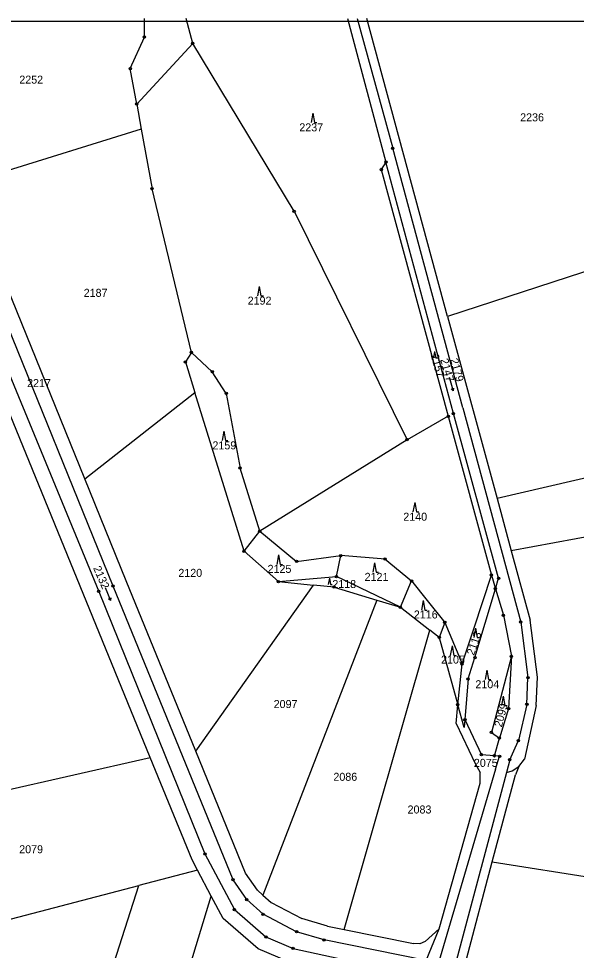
# Model space of a CAD drawing. Extents: x -566461 to -565197, y -1096302 to -1095706.
# Drawn here: x -566039.2 to -565802.3, y -1096101.6 to -1095706 of the extents above; entities that cross this region are included whole.
import ezdxf

# ---------------------------------------------------------------- set-up
doc = ezdxf.new("R2010")
doc.units = 0
for name, color, linetype in [('Vrstva 1', 7, 'Continuous'), ('Vrstva 18', 7, 'Continuous'), ('Vrstva 24', 7, 'Continuous'), ('Vrstva 25', 7, 'Continuous'), ('Vrstva 63', 7, 'Continuous')]:
    doc.layers.add(name, color=color, linetype=linetype)

msp = doc.modelspace()

# ---------------------------------------------------------------- linework, layer by layer
at = {"layer": 'Vrstva 1'}
for p, q in [((-565985.8, -1095713.8), (-565985.75, -1095705.99)), ((-565965.29, -1095716.53), (-565968.02, -1095705.99)), ((-565899.59, -1095705.99), (-565883.2, -1095766.88)), ((-565895.44, -1095705.99), (-565880.3, -1095761.04)), ((-565857.02, -1095832.44), (-565891.34, -1095705.99)), ((-565991.82, -1095727.21), (-565985.8, -1095713.8)), ((-565989.09, -1095742.24), (-565965.29, -1095716.53)), ((-565922.2, -1095787.77), (-565965.29, -1095716.53)), ((-565989.09, -1095742.24), (-565991.82, -1095727.21)), ((-565989.09, -1095742.24), (-565987.16, -1095752.85)), ((-565987.16, -1095752.85), (-566062.52, -1095776.24)), ((-565987.16, -1095752.85), (-565982.54, -1095778.25)), ((-565850.51, -1095871.29), (-565880.3, -1095761.04)), ((-565883.2, -1095766.88), (-565885.21, -1095770.05)), ((-565854.53, -1095873.66), (-565883.2, -1095766.88)), ((-565885.21, -1095770.05), (-565856.75, -1095874.83)), ((-566011.15, -1095901.4), (-566060.56, -1095779.67)), ((-565965.83, -1095847.73), (-565982.54, -1095778.25)), ((-566073.46, -1095783.73), (-566005.23, -1095949.18)), ((-565999.14, -1095946.93), (-566066.64, -1095780.66)), ((-565922.2, -1095787.77), (-565874.23, -1095884.76)), ((-565738.18, -1095793.75), (-565857.02, -1095832.44)), ((-565857.02, -1095832.44), (-565836.03, -1095909.77)), ((-565983.37, -1096019.72), (-566053.24, -1095848.98)), ((-565965.83, -1095847.73), (-565968.4, -1095851.75)), ((-565965.83, -1095847.73), (-565957.02, -1095855.93)), ((-565968.4, -1095851.75), (-565964.37, -1095864.76)), ((-565951.05, -1095865.15), (-565957.02, -1095855.93)), ((-566011.15, -1095901.4), (-565964.37, -1095864.76)), ((-565943.5, -1095932.13), (-565964.37, -1095864.76)), ((-565951.05, -1095865.15), (-565945.16, -1095896.83)), ((-565850.51, -1095871.29), (-565825.94, -1095962.21)), ((-565856.75, -1095874.83), (-565874.23, -1095884.76)), ((-565856.75, -1095874.83), (-565838.43, -1095942.26)), ((-565835.34, -1095943.62), (-565854.53, -1095873.66)), ((-565718.36, -1095882.24), (-565836.03, -1095909.77)), ((-565874.23, -1095884.76), (-565936.81, -1095923.63)), ((-565936.81, -1095923.63), (-565945.16, -1095896.83)), ((-565993.59, -1095944.66), (-566011.15, -1095901.4)), ((-565836.03, -1095909.77), (-565830.02, -1095931.91)), ((-565718.91, -1095911.52), (-565830.02, -1095931.91)), ((-565943.5, -1095932.13), (-565936.81, -1095923.63)), ((-565936.81, -1095923.63), (-565921.15, -1095936.42)), ((-565928.92, -1095944.99), (-565943.5, -1095932.13)), ((-565921.15, -1095936.42), (-565902.44, -1095933.99)), ((-565904.24, -1095942.9), (-565902.44, -1095933.99)), ((-565883.57, -1095935.48), (-565902.44, -1095933.99)), ((-565830.02, -1095931.91), (-565822.01, -1095961.42)), ((-565883.57, -1095935.48), (-565872.35, -1095944.72)), ((-565845.8, -1095964.6), (-565838.43, -1095942.26)), ((-565838.43, -1095942.26), (-565836.68, -1095948.08)), ((-565963.96, -1096017.08), (-565993.59, -1095944.66)), ((-565963.96, -1096017.08), (-565914.03, -1095946.48)), ((-565928.92, -1095944.99), (-565904.24, -1095942.9)), ((-565928.92, -1095944.99), (-565914.03, -1095946.48)), ((-565905.24, -1095947.36), (-565914.03, -1095946.48)), ((-565877.07, -1095955.94), (-565904.24, -1095942.9)), ((-565877.07, -1095955.94), (-565872.35, -1095944.72)), ((-565872.35, -1095944.72), (-565865.64, -1095953.07)), ((-565836.68, -1095948.08), (-565835.34, -1095943.62)), ((-566005.23, -1095949.18), (-565960.14, -1096060.64)), ((-565948.12, -1096071.63), (-565999.14, -1095946.93)), ((-565905.24, -1095947.36), (-565887.08, -1095952.89)), ((-565845.4, -1095977.26), (-565836.68, -1095948.08)), ((-565836.68, -1095948.08), (-565833.29, -1095959.33)), ((-565887.08, -1095952.89), (-565935.5, -1096078.14)), ((-565887.08, -1095952.89), (-565877.07, -1095955.94)), ((-565865.64, -1095953.07), (-565858.2, -1095962.33)), ((-565877.07, -1095955.94), (-565864.53, -1095965.67)), ((-565833.29, -1095959.33), (-565829.89, -1095976.68)), ((-565825.94, -1095962.21), (-565822.87, -1095985.77)), ((-565818.86, -1095985.6), (-565822.01, -1095961.42)), ((-565901, -1096092.75), (-565864.53, -1095965.67)), ((-565860.56, -1095968.75), (-565864.53, -1095965.67)), ((-565858.2, -1095962.33), (-565860.56, -1095968.75)), ((-565858.2, -1095962.33), (-565853.39, -1095973.87)), ((-565850.86, -1095979.94), (-565845.8, -1095964.6)), ((-565860.56, -1095968.75), (-565852.69, -1095997.27)), ((-565853.39, -1095973.87), (-565850.86, -1095979.94)), ((-565848.34, -1095986.31), (-565845.4, -1095977.26)), ((-565829.89, -1095976.68), (-565838.4, -1096009.07)), ((-565829.89, -1095976.68), (-565831.09, -1095998.91)), ((-565852.69, -1095997.27), (-565850.86, -1095979.94)), ((-565823.36, -1095997.16), (-565822.87, -1095985.77)), ((-565819.41, -1095997.69), (-565818.86, -1095985.6)), ((-565848.34, -1095986.31), (-565849.7, -1096003.6)), ((-565853.32, -1096005.31), (-565852.69, -1095997.27)), ((-565849.96, -1096006.91), (-565852.69, -1095997.27)), ((-565823.36, -1095997.16), (-565826.91, -1096012.51)), ((-565819.41, -1095997.69), (-565824.4, -1096020.34)), ((-565831.09, -1095998.91), (-565835.01, -1096011.43)), ((-565853.32, -1096005.31), (-565845.3, -1096022.3)), ((-565849.7, -1096003.6), (-565849.96, -1096006.91)), ((-565849.7, -1096003.6), (-565842.66, -1096018.51)), ((-565838.4, -1096009.07), (-565835.01, -1096011.43)), ((-565837.12, -1096018.99), (-565835.01, -1096011.43)), ((-565828.33, -1096015.6), (-565826.91, -1096012.51)), ((-565942.81, -1096068.77), (-565963.96, -1096017.08)), ((-565830.65, -1096020.64), (-565828.33, -1096015.6)), ((-566099.43, -1096046), (-565983.37, -1096019.72)), ((-565965.58, -1096063.19), (-565983.37, -1096019.72)), ((-565837.12, -1096018.99), (-565842.66, -1096018.51)), ((-565834.95, -1096019.18), (-565837.12, -1096018.99)), ((-565836.72, -1096024.67), (-565834.95, -1096019.18)), ((-565830.65, -1096020.64), (-565832.07, -1096026.09)), ((-565826.72, -1096023.51), (-565824.4, -1096020.34)), ((-565836.72, -1096024.67), (-565860.88, -1096106.94)), ((-565845.3, -1096022.3), (-565843.15, -1096026.07)), ((-565832.07, -1096026.09), (-565829.55, -1096025.32)), ((-565829.55, -1096025.32), (-565826.72, -1096023.51)), ((-565826.72, -1096023.51), (-565828.2, -1096027.12)), ((-565832.07, -1096026.09), (-565854, -1096108.33)), ((-565843.23, -1096030.62), (-565843.15, -1096026.07)), ((-565838.03, -1096063.98), (-565828.2, -1096027.12)), ((-565860.59, -1096092.38), (-565843.23, -1096030.62)), ((-565960.14, -1096060.64), (-565947.56, -1096084.25)), ((-565963.24, -1096067.58), (-565965.58, -1096063.19)), ((-565849.04, -1096105.26), (-565838.03, -1096063.98)), ((-565838.03, -1096063.98), (-565736.97, -1096079.98)), ((-565963.24, -1096067.58), (-565988.25, -1096074.11)), ((-565957.4, -1096078.54), (-565963.24, -1096067.58)), ((-565937.82, -1096076.07), (-565942.81, -1096068.77)), ((-565942.36, -1096080.06), (-565948.12, -1096071.63)), ((-566049.51, -1096090.1), (-565988.25, -1096074.11)), ((-566039.72, -1096234.72), (-565988.25, -1096074.11)), ((-565937.82, -1096076.07), (-565935.5, -1096078.14)), ((-566002.86, -1096227.33), (-565957.4, -1096078.54)), ((-565952.33, -1096088.05), (-565957.4, -1096078.54)), ((-565935.41, -1096086.27), (-565942.36, -1096080.06)), ((-565935.5, -1096078.14), (-565931.97, -1096081.29)), ((-565947.56, -1096084.25), (-565934.22, -1096095.86)), ((-565931.97, -1096081.29), (-565918.93, -1096088.11)), ((-565937.44, -1096101.01), (-565952.33, -1096088.05)), ((-565921.19, -1096093.7), (-565935.41, -1096086.27)), ((-565908.08, -1096091.32), (-565918.93, -1096088.11)), ((-565908.08, -1096091.32), (-565901, -1096092.75)), ((-565901, -1096092.75), (-565871.5, -1096098.69)), ((-565860.59, -1096092.38), (-565866.49, -1096097.81)), ((-565866.09, -1096105.89), (-565860.59, -1096092.38)), ((-565934.22, -1096095.86), (-565922.65, -1096100.77)), ((-565909.52, -1096097.15), (-565921.19, -1096093.7)), ((-565922.65, -1096100.77), (-565855.22, -1096115.35)), ((-565866.09, -1096105.89), (-565909.52, -1096097.15)), ((-565868.87, -1096098.76), (-565871.5, -1096098.69)), ((-565866.49, -1096097.81), (-565868.87, -1096098.76)), ((-565924.47, -1096106.51), (-565937.44, -1096101.01))]:
    msp.add_line(p, q, dxfattribs=at)
at = {"layer": 'Vrstva 24'}
for centre, radius in [((-565985.8, -1095713.8), 0.5), ((-565985.8, -1095713.8), 0.0327), ((-565965.29, -1095716.53), 0.5), ((-565965.29, -1095716.53), 0.0327), ((-565991.82, -1095727.21), 0.5), ((-565991.82, -1095727.21), 0.0327), ((-565989.09, -1095742.24), 0.5), ((-565989.09, -1095742.24), 0.0327), ((-565880.3, -1095761.04), 0.5), ((-565880.3, -1095761.04), 0.0327), ((-565883.2, -1095766.88), 0.5), ((-565883.2, -1095766.88), 0.0327), ((-565885.21, -1095770.05), 0.5), ((-565885.21, -1095770.05), 0.0327), ((-565982.54, -1095778.25), 0.5), ((-565982.54, -1095778.25), 0.0327), ((-565922.2, -1095787.77), 0.5), ((-565922.2, -1095787.77), 0.0327), ((-565965.83, -1095847.73), 0.5), ((-565968.4, -1095851.75), 0.5), ((-565965.83, -1095847.73), 0.0327), ((-565968.4, -1095851.75), 0.0327), ((-565957.02, -1095855.93), 0.5), ((-565957.02, -1095855.93), 0.0327), ((-565951.05, -1095865.15), 0.5), ((-565951.05, -1095865.15), 0.0327), ((-565856.75, -1095874.83), 0.5), ((-565856.75, -1095874.83), 0.0327), ((-565854.53, -1095873.66), 0.5), ((-565854.53, -1095873.66), 0.0327), ((-565874.23, -1095884.76), 0.5), ((-565874.23, -1095884.76), 0.0327), ((-565945.16, -1095896.83), 0.5), ((-565945.16, -1095896.83), 0.0327), ((-565936.81, -1095923.63), 0.5), ((-565936.81, -1095923.63), 0.0327), ((-565943.5, -1095932.13), 0.5), ((-565943.5, -1095932.13), 0.0327), ((-565902.44, -1095933.99), 0.5), ((-565902.44, -1095933.99), 0.0327), ((-565921.15, -1095936.42), 0.5), ((-565921.15, -1095936.42), 0.0327), ((-565883.57, -1095935.48), 0.5), ((-565883.57, -1095935.48), 0.0327), ((-565904.24, -1095942.9), 0.5), ((-565838.43, -1095942.26), 0.5), ((-565838.43, -1095942.26), 0.0327), ((-565999.14, -1095946.93), 0.5), ((-565928.92, -1095944.99), 0.5), ((-565928.92, -1095944.99), 0.0327), ((-565904.24, -1095942.9), 0.0327), ((-565872.35, -1095944.72), 0.5), ((-565872.35, -1095944.72), 0.0327), ((-565835.34, -1095943.62), 0.5), ((-565835.34, -1095943.62), 0.0327), ((-566005.23, -1095949.18), 0.5), ((-566005.23, -1095949.18), 0.0327), ((-565999.14, -1095946.93), 0.0327), ((-565905.24, -1095947.36), 0.5), ((-565905.24, -1095947.36), 0.0327), ((-565836.68, -1095948.08), 0.5), ((-565836.68, -1095948.08), 0.0327), ((-565877.07, -1095955.94), 0.5), ((-565877.07, -1095955.94), 0.0327), ((-565858.2, -1095962.33), 0.5), ((-565858.2, -1095962.33), 0.0327), ((-565833.29, -1095959.33), 0.5), ((-565833.29, -1095959.33), 0.0327), ((-565825.94, -1095962.21), 0.5), ((-565825.94, -1095962.21), 0.0327), ((-565860.56, -1095968.75), 0.5), ((-565860.56, -1095968.75), 0.0327), ((-565845.4, -1095977.26), 0.5), ((-565845.4, -1095977.26), 0.0327), ((-565829.89, -1095976.68), 0.5), ((-565829.89, -1095976.68), 0.0327), ((-565850.86, -1095979.94), 0.5), ((-565850.86, -1095979.94), 0.0327), ((-565848.34, -1095986.31), 0.5), ((-565822.87, -1095985.77), 0.5), ((-565822.87, -1095985.77), 0.0327), ((-565848.34, -1095986.31), 0.0327), ((-565852.69, -1095997.27), 0.5), ((-565852.69, -1095997.27), 0.0327), ((-565823.36, -1095997.16), 0.5), ((-565823.36, -1095997.16), 0.0327), ((-565831.09, -1095998.91), 0.5), ((-565831.09, -1095998.91), 0.0327), ((-565849.7, -1096003.6), 0.5), ((-565849.7, -1096003.6), 0.0327), ((-565838.4, -1096009.07), 0.5), ((-565838.4, -1096009.07), 0.0327), ((-565835.01, -1096011.43), 0.5), ((-565835.01, -1096011.43), 0.0327), ((-565826.91, -1096012.51), 0.5), ((-565826.91, -1096012.51), 0.0327), ((-565842.66, -1096018.51), 0.5), ((-565842.66, -1096018.51), 0.0327), ((-565837.12, -1096018.99), 0.5), ((-565837.12, -1096018.99), 0.0327), ((-565834.95, -1096019.18), 0.5), ((-565834.95, -1096019.18), 0.0327), ((-565830.65, -1096020.64), 0.5), ((-565830.65, -1096020.64), 0.0327), ((-565960.14, -1096060.64), 0.5), ((-565960.14, -1096060.64), 0.0327), ((-565948.12, -1096071.63), 0.5), ((-565948.12, -1096071.63), 0.0327), ((-565942.36, -1096080.06), 0.5), ((-565942.36, -1096080.06), 0.0327), ((-565947.56, -1096084.25), 0.5), ((-565947.56, -1096084.25), 0.0327), ((-565935.41, -1096086.27), 0.5), ((-565935.41, -1096086.27), 0.0327), ((-565934.22, -1096095.86), 0.5), ((-565934.22, -1096095.86), 0.0327), ((-565921.19, -1096093.7), 0.5), ((-565921.19, -1096093.7), 0.0327), ((-565909.52, -1096097.15), 0.5), ((-565922.65, -1096100.77), 0.5), ((-565922.65, -1096100.77), 0.0327), ((-565909.52, -1096097.15), 0.0327)]:
    msp.add_circle(centre, radius, dxfattribs=at)
at = {"layer": 'Vrstva 25'}
for p, q in [((-565914.29, -1095746.14), (-565915.03, -1095750.14)), ((-565914.29, -1095746.14), (-565913.56, -1095750.14)), ((-565913.56, -1095750.14), (-565912.56, -1095750.14)), ((-565937.02, -1095819.71), (-565937.76, -1095823.71)), ((-565937.02, -1095819.71), (-565936.29, -1095823.71)), ((-565936.29, -1095823.71), (-565935.29, -1095823.71)), ((-565862.52, -1095847.32), (-565863.01, -1095850)), ((-565862.52, -1095847.32), (-565862.02, -1095850)), ((-565862.02, -1095850), (-565861.35, -1095850)), ((-565856.34, -1095858.19), (-565854.72, -1095863.97)), ((-565952.04, -1095881.17), (-565952.78, -1095885.17)), ((-565952.04, -1095881.17), (-565951.31, -1095885.17)), ((-565951.31, -1095885.17), (-565950.31, -1095885.17)), ((-565871.01, -1095911.46), (-565871.74, -1095915.46)), ((-565871.01, -1095911.46), (-565870.28, -1095915.46)), ((-565870.28, -1095915.46), (-565869.28, -1095915.46)), ((-565928.85, -1095933.72), (-565929.58, -1095937.72)), ((-565928.85, -1095933.72), (-565928.12, -1095937.72)), ((-565928.12, -1095937.72), (-565927.12, -1095937.72)), ((-565888.04, -1095937), (-565888.78, -1095941)), ((-565888.04, -1095937), (-565887.31, -1095941)), ((-565887.31, -1095941), (-565886.31, -1095941)), ((-565907.2, -1095943.63), (-565907.69, -1095946.31)), ((-565907.2, -1095943.63), (-565906.7, -1095946.31)), ((-565906.7, -1095946.31), (-565906.03, -1095946.31)), ((-566002.42, -1095947.53), (-566000.17, -1095953.09)), ((-565867.41, -1095953.1), (-565868.15, -1095957.1)), ((-565867.41, -1095953.1), (-565866.68, -1095957.1)), ((-565866.68, -1095957.1), (-565865.68, -1095957.1)), ((-565845.14, -1095964.72), (-565845.88, -1095968.72)), ((-565845.14, -1095964.72), (-565844.41, -1095968.72)), ((-565844.41, -1095968.72), (-565843.41, -1095968.72)), ((-565855.15, -1095972.36), (-565855.89, -1095976.36)), ((-565855.15, -1095972.36), (-565854.42, -1095976.36)), ((-565854.42, -1095976.36), (-565853.42, -1095976.36)), ((-565840.38, -1095982.59), (-565841.11, -1095986.59)), ((-565840.38, -1095982.59), (-565839.65, -1095986.59)), ((-565839.65, -1095986.59), (-565838.65, -1095986.59)), ((-565833.44, -1095993.66), (-565834.18, -1095997.66)), ((-565833.44, -1095993.66), (-565832.71, -1095997.66)), ((-565832.71, -1095997.66), (-565831.71, -1095997.66))]:
    msp.add_line(p, q, dxfattribs=at)
for points in [[(-565854.51, -1095862.87), (-565854.72, -1095863.97), (-565855.47, -1095863.14)], [(-566000.08, -1095951.98), (-566000.17, -1095953.09), (-566001, -1095952.35)]]:
    msp.add_lwpolyline(points, dxfattribs=at)
at = {"layer": 'Vrstva 63'}
msp.add_line((-566458.38, -1095707.03), (-565198.38, -1095707.03), dxfattribs=at)

# ---------------------------------------------------------------- texts
at = {"layer": 'Vrstva 18'}
for s, p in [('2252', (-566038.96, -1095733.59)), ('2236', (-565826.2, -1095749.6)), ('2237', (-565920.01, -1095753.85)), ('2187', (-566011.61, -1095824.11)), ('2192', (-565941.95, -1095827.42)), ('2217', (-566035.66, -1095862.42)), ('2159', (-565956.91, -1095888.88)), ('2140', (-565875.84, -1095919.17)), ('2125', (-565933.49, -1095941.31)), ('2120', (-565971.39, -1095943.01)), ('2121', (-565892.27, -1095944.71)), ('2118', (-565905.99, -1095947.75)), ('2116', (-565871.36, -1095960.68)), ('2105', (-565859.79, -1095979.83)), ('2104', (-565845.21, -1095990.3)), ('2097', (-565930.91, -1095998.71)), ('2075', (-565845.86, -1096023.68)), ('2086', (-565905.53, -1096029.59)), ('2083', (-565874.02, -1096043.48)), ('2079', (-566039, -1096060.36))]:
    msp.add_text(s, height=3.4, dxfattribs=at).set_placement(p)
for s, rotation, p in [('2157', 285.3, (-565864.22, -1095848.89)), ('2147', 285.3, (-565860.13, -1095850.75)), ('2179', 285.3, (-565855.95, -1095850.71)), ('2132', 293.4, (-566007.65, -1095939.24)), ('2113', 71.1, (-565845.81, -1095976.58)), ('2099', 74.7, (-565834.05, -1096007.06))]:
    msp.add_text(s, height=3.4, rotation=rotation, dxfattribs=at).set_placement(p)

doc.saveas('drawing.dxf')
